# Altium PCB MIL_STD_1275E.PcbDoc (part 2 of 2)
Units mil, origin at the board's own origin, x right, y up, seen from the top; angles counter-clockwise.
Board outline 4000 x 3000 mil, 4 copper layers (Top Layer 1, GND, Signal Layer, Bottom Layer 1), stack 61.2 mil thick; 67 components, 20 nets, 127 pads, 432 vias.
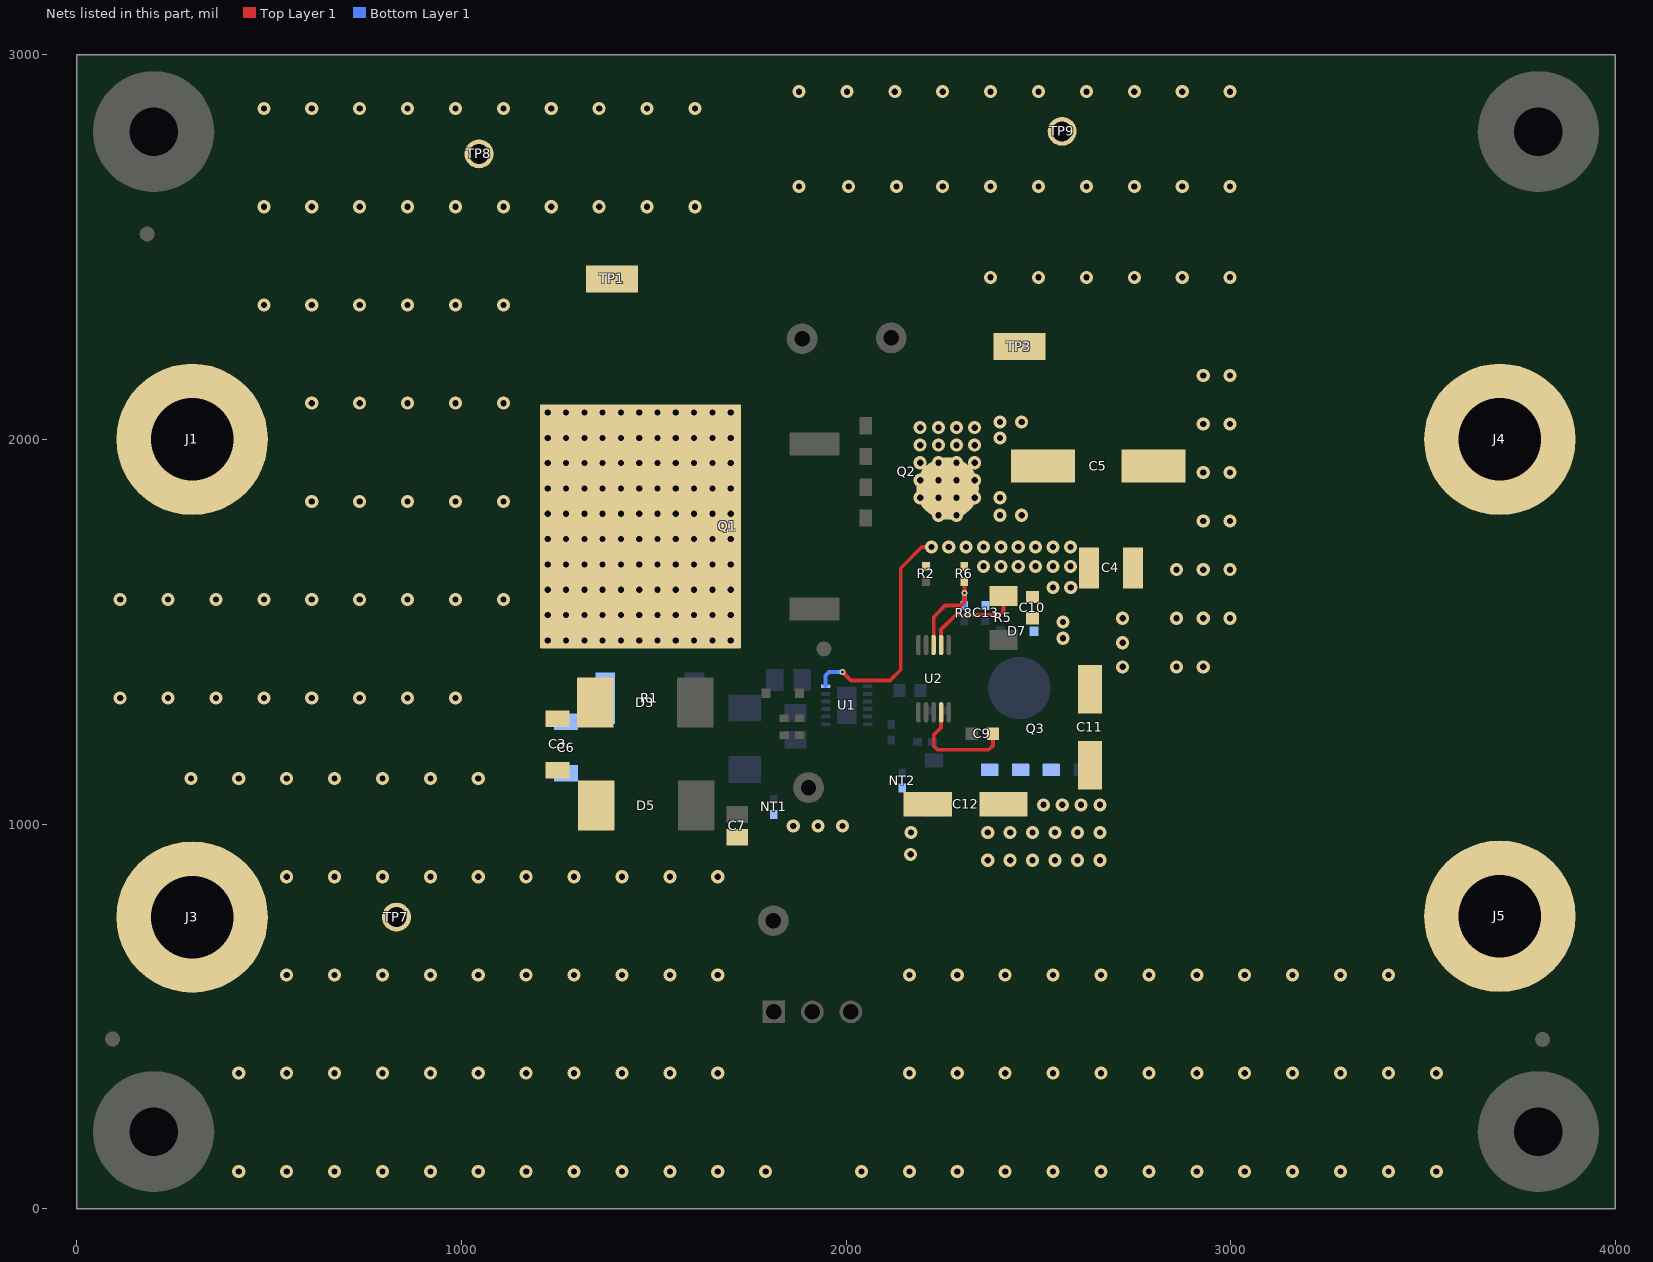
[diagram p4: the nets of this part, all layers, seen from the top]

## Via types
v1: diameter 34, hole 16, Top Layer 1 to Bottom Layer 1, 391 vias
v2: diameter 34, hole 16, Top Layer 1 to Bottom Layer 1, tented both sides, 20 vias
v3: diameter 16, hole 8, Top Layer 1 to Bottom Layer 1, tented both sides, 16 vias
v4: diameter 19.68, hole 7.87, Top Layer 1 to Bottom Layer 1, 3 vias
v5: diameter 34, hole 16, Top Layer 1 to Bottom Layer 1, tented top, 2 vias

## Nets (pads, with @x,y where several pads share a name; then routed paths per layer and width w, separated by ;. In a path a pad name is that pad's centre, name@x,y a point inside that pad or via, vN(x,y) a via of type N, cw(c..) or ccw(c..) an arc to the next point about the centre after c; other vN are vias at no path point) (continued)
SGND: C3.2 C4.2 C5.2 C6.2 C7.2 C10.2 C11.2 C12.2 D5.1 D7.1 J3.1 J5.1 NT1.1 NT2.1 TP7.1 TP8.1 TP9.1
  other v1: 421.23,96.7 545.77,96.7 670.31,96.7 794.85,96.7 919.39,96.7 1043.94,96.7 1168.48,96.7 1293.02,96.7 1417.56,96.7 1542.1,96.7 1666.64,96.7 1791.18,96.7 2040.27,96.7 2164.81,96.7 2289.35,96.7 2413.89,96.7 2538.43,96.7 2662.97,96.7 2787.51,96.7 2912.05,96.7 3036.6,96.7 3161.14,96.7 3285.68,96.7 3410.22,96.7 3534.76,96.7 421.23,352.06 545.77,352.06 670.31,352.06 794.85,352.06 919.39,352.06 1043.94,352.06 1168.48,352.06 1293.02,352.06 1417.56,352.06 1542.1,352.06 1666.64,352.06 2164.81,352.06 2289.35,352.06 2413.89,352.06 2538.43,352.06 2662.97,352.06 2787.51,352.06 2912.05,352.06 3036.6,352.06 3161.14,352.06 3285.68,352.06 3410.22,352.06 3534.76,352.06 545.77,607.42 670.31,607.42 794.85,607.42 919.39,607.42 1043.94,607.42 1168.48,607.42 1293.02,607.42 1417.56,607.42 1542.1,607.42 1666.64,607.42 2164.81,607.42 2289.35,607.42 2413.89,607.42 2538.43,607.42 2662.97,607.42 2787.51,607.42 2912.05,607.42 3036.6,607.42 3161.14,607.42 3285.68,607.42 3410.22,607.42 545.77,862.78 670.31,862.78 794.85,862.78 919.39,862.78 1043.94,862.78 1168.48,862.78 1293.02,862.78 1417.56,862.78 1542.1,862.78 1666.64,862.78 296.69,1118.14 421.23,1118.14 545.77,1118.14 670.31,1118.14 794.85,1118.14 919.39,1118.14 1043.94,1118.14 2859.03,1408.73 2928.86,1408.73 2859.03,1534.94 2928.86,1534.94 2998.7,1534.94 2859.03,1661.15 2928.86,1661.15 2998.7,1661.15 2928.86,1787.36 2998.7,1787.36 2928.86,1913.57 2998.7,1913.57 2928.86,2039.78 2998.7,2039.78 2928.86,2165.99 2998.7,2165.99 2375.99,2421.35 2500.53,2421.35 2625.07,2421.35 2749.61,2421.35 2874.15,2421.35 2998.7,2421.35 1877.82,2657.36 2007.02,2657.36 2131.56,2657.36 2251.45,2657.36 2375.99,2657.36 2500.53,2657.36 2625.07,2657.36 2749.61,2657.36 2874.15,2657.36 2998.7,2657.36 1877.82,2904.01 2002.37,2904.01 2126.91,2904.01 2251.45,2904.01 2375.99,2904.01 2500.53,2904.01 2625.07,2904.01 2749.61,2904.01 2874.15,2904.01 2998.7,2904.01
  other v2: 2168.18,921.17 2168.57,977.8 1862.79,994.82 1926.99,994.82 1991.18,994.82 2719.36,1408.73 2719.36,1471.22 2563.92,1483.02 2563.92,1525.13 2719.36,1534.94
UVLO: R6.1 R8.2 U2.3 | length 255.7
  Top Layer 1 w10: U2.3@2227.71,1465.44 2228.06,1465.78 2228.06,1538.53 2257.33,1567.8 2299.04,1567.8 2307.9,1576.66 v3(2307.9,1600.64) R6.1@2307.9,1630.64
  Bottom Layer 1 w10: R8.2@2307.9,1567.8 v3(2307.9,1600.64)
VIN: C3.1 C6.1 D3.1 J1.1 Q1.4 R1.2 TP1.1
  other v1: 112.85,1328.05 237.39,1328.05 361.93,1328.05 486.47,1328.05 611.01,1328.05 735.56,1328.05 860.1,1328.05 984.64,1328.05 1224.62,1477.31 1272.17,1477.31 1319.73,1477.31 1367.28,1477.31 1414.84,1477.31 1462.39,1477.31 1509.95,1477.31 1557.5,1477.31 1605.06,1477.31 1652.61,1477.31 1700.16,1477.31 1224.62,1543.15 1272.17,1543.15 1319.73,1543.15 1367.28,1543.15 1414.84,1543.15 1462.39,1543.15 1509.95,1543.15 1557.5,1543.15 1605.06,1543.15 1652.61,1543.15 1700.16,1543.15 112.85,1583.41 237.39,1583.41 361.93,1583.41 486.47,1583.41 611.01,1583.41 735.56,1583.41 860.1,1583.41 984.64,1583.41 1109.18,1583.41 1224.62,1608.98 1272.17,1608.98 1319.73,1608.98 1367.28,1608.98 1414.84,1608.98 1462.39,1608.98 1509.95,1608.98 1557.5,1608.98 1605.06,1608.98 1652.61,1608.98 1700.16,1608.98 1224.62,1674.81 1272.17,1674.81 1319.73,1674.81 1367.28,1674.81 1414.84,1674.81 1462.39,1674.81 1509.95,1674.81 1557.5,1674.81 1605.06,1674.81 1652.61,1674.81 1700.16,1674.81 1224.62,1740.65 1272.17,1740.65 1319.73,1740.65 1367.28,1740.65 1414.84,1740.65 1462.39,1740.65 1509.95,1740.65 1557.5,1740.65 1605.06,1740.65 1652.61,1740.65 1700.16,1740.65 1224.62,1806.48 1272.17,1806.48 1319.73,1806.48 1367.28,1806.48 1414.84,1806.48 1462.39,1806.48 1509.95,1806.48 1557.5,1806.48 1605.06,1806.48 1652.61,1806.48 1700.16,1806.48 611.01,1838.77 735.56,1838.77 860.1,1838.77 984.64,1838.77 1109.18,1838.77 1224.62,1872.32 1272.17,1872.32 1319.73,1872.32 1367.28,1872.32 1414.84,1872.32 1462.39,1872.32 1509.95,1872.32 1557.5,1872.32 1605.06,1872.32 1652.61,1872.32 1700.16,1872.32 1224.62,1938.15 1272.17,1938.15 1319.73,1938.15 1367.28,1938.15 1414.84,1938.15 1462.39,1938.15 1509.95,1938.15 1557.5,1938.15 1605.06,1938.15 1652.61,1938.15 1700.16,1938.15 1224.62,2003.99 1272.17,2003.99 1319.73,2003.99 1367.28,2003.99 1414.84,2003.99 1462.39,2003.99 1509.95,2003.99 1557.5,2003.99 1605.06,2003.99 1652.61,2003.99 1700.16,2003.99 1224.62,2069.82 1272.17,2069.82 1319.73,2069.82 1367.28,2069.82 1414.84,2069.82 1462.39,2069.82 1509.95,2069.82 1557.5,2069.82 1605.06,2069.82 1652.61,2069.82 1700.16,2069.82 611.01,2094.13 735.56,2094.13 860.1,2094.13 984.64,2094.13 1109.18,2094.13 486.47,2349.49 611.01,2349.49 735.56,2349.49 860.1,2349.49 984.64,2349.49 1109.18,2349.49 486.47,2604.85 611.01,2604.85 735.56,2604.85 860.1,2604.85 984.64,2604.85 1109.18,2604.85 1233.72,2604.85 1358.26,2604.85 1482.8,2604.85 1607.34,2604.85 486.47,2860.21 611.01,2860.21 735.56,2860.21 860.1,2860.21 984.64,2860.21 1109.18,2860.21 1233.72,2860.21 1358.26,2860.21 1482.8,2860.21 1607.34,2860.21
VOUT: C9.1 C11.1 C12.1 J4.1 Q3.2 Q3.3 Q3.4 U2.9 | length 288.9
  Top Layer 1 w10: U2.9@2247.4,1290.24 2247.4,1250.33 2228.22,1231.16 2228.22,1202.35 2237.6,1192.98 2371.32,1192.98 2382.02,1203.68 C9.1@2382.02,1234.67
  other v1: 2485.18,977.8 2543.48,977.8 2601.77,977.8 2660.06,977.8 2513.2,1049.93 2562.15,1049.93 2611.1,1049.93 2660.06,1049.93
  other v2: 2368.6,905.67 2426.89,905.67 2485.18,905.67 2543.48,905.67 2601.77,905.67 2660.06,905.67 2368.6,977.8 2426.89,977.8
VOUT_LM7480: C4.1 C5.1 C10.1 C13.2 Q2.5 R2.2 R5.1 R6.2 TP3.1 U1.12 U2.2 | length 875.5
  Top Layer 1 w10: v3(1990.48,1395.16) 2012.54,1373.11 2114.16,1373.11 2142.21,1401.16 2142.21,1665.01 2197.06,1719.85 2221.67,1719.85 v1(2221.99,1720.17) ; U2.2@2247.4,1465.44 2247.4,1505.53 2285.83,1543.96 2399.79,1543.96 2409.15,1553.33 R5.1@2409.15,1592.75
  Bottom Layer 1 w10: U1.12@1946.86,1357.98 1946.86,1385.99 1956.04,1395.16 v3(1990.48,1395.16)
  other v1: 2538.2,1614.96 2584.41,1614.96 2357.51,1670.01 2402.68,1670.01 2447.85,1670.01 2493.03,1670.01 2538.2,1670.01 2583.37,1670.01 2267.17,1720.17 2312.34,1720.17 2357.51,1720.17 2402.68,1720.17 2447.85,1720.17 2493.03,1720.17 2538.2,1720.17 2583.37,1720.53 2240.11,1802.75 2287.38,1802.75 2400.07,1802.75 2456.79,1802.75 2192.85,1848.28 2240.11,1848.28 2287.38,1848.28 2334.64,1848.28 2400.07,1848.28 2192.85,1893.8 2240.11,1893.8 2287.38,1893.8 2334.64,1893.8 2192.85,1939.33 2240.11,1939.33 2287.38,1939.33 2334.64,1939.33 2192.85,1984.85 2240.11,1984.85 2287.38,1984.85 2334.64,1984.85 2400.07,2003.99 2192.85,2030.38 2240.11,2030.38 2287.38,2030.38 2334.64,2030.38 2400.07,2045.33 2456.79,2045.33
pads on no net: FID1.1 FID2.1 FID3.1 H1.1 H2.1 H3.1 H4.1 H5.0 H6.0 H7.0 H8.0 LBL1.0 U1.13 U2.8
copper on no net: | length 58.6
  Top Layer 1 w30: 1249.99,1081.39 1249.99,1139.95
  other v4: 2001.59,1269.39 2000.59,1308.76 2001.59,1348.13

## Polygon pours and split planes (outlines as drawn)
SGND on Bottom Layer 1 "BOTTOM_LAYER_1_NONET_P017" (solid, shelved, pour order 17): 24.65,2880.92 118.64,2974.91 3850.18,2974.91 3983.2,2841.89 3975.12,2833.81 3975.12,119.94 3879.15,23.97 150.2,23.97 24.65,149.52
VOUT on Bottom Layer 1 "BOTTOM_LAYER_1_VOUT_P020" (solid, pour order 20): 2301.92,1156.06 2312.4,1166.54 2554.04,1166.54 2570.25,1150.32 2570.25,1109.27 2580.56,1098.95 2660.24,1098.95 2696.8,1062.4 2696.8,889.4 2670.36,862.97 2317.35,862.97 2301.92,878.4
NetQ3_5 on Bottom Layer 1 "BOTTOM_LAYER_1_NETQ3_5_P008" (solid, pour order 8): 2301.92,1430.36 2328.36,1456.79 2646.85,1456.79 2667.38,1436.26 2667.38,1220.31 2648.02,1200.96 2321.41,1200.96 2301.92,1220.45
AGND2 on Bottom Layer 1 "BOTTOM_LAYER_1_AGND2_P001" (solid, pour order 1): 2113.97,1156.71 2128.59,1171.33 2180.92,1171.33 2209.57,1199.98 2209.57,1229.23 2241.39,1261.05 2241.39,1421.92 2174.34,1488.97 2174.34,1531.89 2185.78,1543.34 2408.82,1543.34 2429.31,1522.85 2429.31,1477.23 2422.14,1470.06 2322.77,1470.06 2293.29,1440.57 2293.29,1277.61 2268.73,1253.05 2268.73,1144.58 2237.35,1113.2 2117.77,1113.2 2113.97,1117.01
AGND1 on Bottom Layer 1 "BOTTOM_LAYER_1_AGND1_P002" (solid, pour order 2): 1721.12,1247.77 1918.8,1247.77 1936.41,1265.38 1960.42,1265.38 1993.11,1232.69 2131.99,1232.69 2135.05,1235.75 2135.05,1295.97 2169.87,1330.79 2169.87,1361.37 2177.64,1369.14 2212.69,1369.14 2219.83,1357.98 2219.83,1330.45 2200.59,1311.21 2200.59,1283.73 2161.54,1244.69 2161.54,1187.82 2154.02,1180.3 2115.74,1180.3 1981.54,1046.1 1712.52,1046.1 1685.53,1073.09 1685.53,1212.19
VIN on Bottom Layer 1 "BOTTOM_LAYER_1_VIN_P012" (solid, pour order 12): 1419.38,1223.83 1465.63,1270.08 1465.63,1385.52 1537.36,1457.25 1720.34,1457.25 1729.2,1466.11 1729.2,2951.05 1705.34,2974.91 54.77,2974.91 25.55,2945.69 25.55,1258.08 59.8,1223.83
VOUT_LM7480 on Bottom Layer 1 "BOTTOM_LAYER_1_VOUT_LM7480_P006" (solid, pour order 6): 2137.24,2091.37 2137.24,1662.4 2145.12,1654.51 2322.97,1654.51 2332.17,1645.32 2332.17,1571.09 2352.12,1551.14 2635.82,1551.14 2688.98,1604.31 2688.98,1777.06 2616,1850.04 2616,2090.72 2610.1,2096.61 2142.48,2096.61
NetC8_1 on Bottom Layer 1 "BOTTOM_LAYER_1_NETC8_1_P004" (solid, pour order 4): 1785.88,2323.89 2015.64,2323.89 2021.32,2318.21 2021.32,2015.72 2042.34,1994.7 2073.37,1994.7 2084.9,1983.17 2084.9,1407.41 2073.95,1396.46 2017.13,1396.46 2011.77,1401.83 2011.77,1600.66 2000.93,1611.5 1844.47,1611.5 1830.08,1597.11 1830.08,1516.55 1895.72,1450.91 1895.72,1429.83 1888.24,1422.35 1788.02,1422.35 1778.72,1431.65 1778.72,2316.73
NetC1_1 on Bottom Layer 1 "BOTTOM_LAYER_1_NETC1_1_P000" (solid, pour order 0): 1845.07,1403.51 1841.8,1406.78 1578.91,1406.77 1575.26,1403.13 1575.26,1257.47 1581.19,1251.53 1712.45,1251.53 1716.84,1255.93 1889.7,1255.93 1899.64,1265.87 1899.64,1300.83 1911.23,1312.42 1959.3,1312.42 1960.52,1313.64 1960.52,1323.31 1959.3,1324.53 1918.96,1324.53 1864.59,1324.53 1845.07,1344.05
SGND on Top Layer 1 "TOP_LAYER_1_SGND_P016" (solid, pour order 16): 24.65,2880.92 118.64,2974.91 3850.18,2974.91 3983.2,2841.89 3975.12,2833.81 3975.12,119.94 3879.15,23.97 150.2,23.97 24.65,149.52
VOUT on Top Layer 1 "TOP_LAYER_1_VOUT_P014" (solid, pour order 14): 2301.92,878.4 2301.92,1156.06 2354.33,1208.46 2354.33,1246.35 2376.5,1268.53 2516.15,1268.53 2555.45,1229.23 2816.02,1229.23 3043.59,1456.79 3043.59,2935.23 3088.59,2980.23 3923.35,2980.23 3924.96,2981.84 3973.82,2932.98 3973.82,1086.69 3949,1061.87 3320.26,1061.87 3121.36,862.97 2317.35,862.97
NetC8_1 on Top Layer 1 "TOP_LAYER_1_NETC8_1_P003" (solid, pour order 3): 1785.88,2323.89 2014.83,2323.89 2021.32,2317.4 2021.32,2015.72 2042.34,1994.7 2073.37,1994.7 2081.96,1986.11 2081.96,1758.47 2113.16,1727.27 2113.16,1409.35 2095.31,1391.51 2022.09,1391.51 2011.77,1401.83 2011.77,1600.66 2000.93,1611.5 1844.47,1611.5 1830.08,1597.11 1830.08,1516.55 1895.5,1451.13 1895.5,1405.82 1876.12,1386.44 1823.93,1386.44 1778.79,1431.58 1778.79,2316.8
VIN on Top Layer 1 "TOP_LAYER_1_VIN_P011" (solid, pour order 11): 1419.38,1223.83 1465.63,1270.08 1465.63,1385.52 1513.73,1433.62 1713.29,1433.62 1729.2,1449.53 1729.2,2951.05 1705.34,2974.91 54.77,2974.91 25.55,2945.69 25.55,1258.08 59.8,1223.83
NetQ3_5 on Top Layer 1 "TOP_LAYER_1_NETQ3_5_P007" (solid, pour order 7): 2488.22,1504.33 2533.75,1458.81 2533.75,1286.12 2528.11,1280.49 2307.94,1280.49 2301.92,1286.51 2301.92,1496.51 2309.74,1504.33
VOUT_LM7480 on Top Layer 1 "TOP_LAYER_1_VOUT_LM7480_P005" (solid, pour order 5): 2137.24,2165.3 2137.24,1662.4 2145.12,1654.51 2322.97,1654.51 2332.17,1645.32 2332.17,1584.61 2349.71,1567.07 2651.74,1567.07 2688.98,1604.31 2688.98,1777.06 2616,1850.04 2616,2288.87 2606.16,2298.71 2270.65,2298.71
SGND on GND "GND_SGND_P018" (solid, pour order 18): 24.65,2880.92 118.64,2974.91 3850.18,2974.91 3983.2,2841.89 3975.12,2833.81 3975.12,119.94 3879.15,23.97 150.2,23.97 24.65,149.52
SGND on Signal Layer "SIGNAL_LAYER_SGND_P019" (solid, pour order 19): 24.65,2880.92 118.64,2974.91 3850.18,2974.91 3983.2,2841.89 3975.12,2833.81 3975.12,119.94 3879.15,23.97 150.2,23.97 24.65,149.52

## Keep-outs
Top Layer 1:
  region: 1549.17,1385.98 1554,1390.81 1659.07,1390.81 1665.49,1384.38 1665.49,1091.28 1680.9,1075.86 1755.93,1075.86 1765.49,1066.3 1765.49,1002.36 1758.15,995.02 1676.41,995.02 1641.96,960.57 1554.3,960.57 1549.17,965.7
GND:
  region: 1151.7,2090.38 1190.99,2129.67 1707.72,2129.67 1759.45,2077.94 1759.45,1446.96 1728.26,1415.77 1184.67,1415.77 1151.7,1448.73
Signal Layer:
  region: 1151.3,2090.76 1190.59,2130.05 1707.32,2130.05 1759.05,2078.32 1759.05,1447.34 1727.85,1416.15 1184.26,1416.15 1151.3,1449.11
Keep-Out Layer:
  text ".Layer_Name" at 577,-858.49 h60

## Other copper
Top Layer 1:
  text ".Layer_Name" at 577,-858.49 h60
Bottom Layer 1:
  text ".Layer_Name" at 577,-858.49 h60

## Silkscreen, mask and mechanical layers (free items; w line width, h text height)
Top Overlay:
  lines w10: 1196.77,916.87 2776.34,916.87 2776.34,1702.08 2902.15,1827.89 2902.15,2021.71 2825.89,2097.97 2771.57,2097.97 1196.77,2097.97 1196.77,916.87
  text "SGND" at 2651.7,2810.96 h60
  text "SGND" at 741.75,2742.46 h60
  text "OUT" at 1782.69,2400.19 h60
  text "DGATE" at 2075.85,2400.19 h60
  text "VOUT" at 3490.14,2304.42 h60
  text "VIN" at 1323.85,2280.12 h60
  text "VOUT_LM7480" at 2578.92,2261.6 h60
  text "VIN" at 99.65,2254.98 h60
  text "30mm" at 1166.15,1294.19 h60 r90
  text "SGND" at 91.73,1006.75 h60
  text "AGND1" at 1869.85,989.48 h60
  text "40mm" at 1934.9,834.34 h60
  text "SGND" at 914.08,742.62 h60
  text "VS" at 1602.81,742.62 h60
  text "SGND" at 3414.24,403.45 h60
  text "VS" at 1835.92,318.25 h60 r90
  text "'.PRJ_Number'.PCB_Rev" at 2328.39,171.27 h108.27
  text "AGND1" at 2047.31,158.3 h60 r90
  text "ENABLE" at 1941.13,78.33 h60 r90
  text ".Layer_Name" at 577,-858.49 h60
Bottom Overlay:
  lines w10: 1196.77,902.12 2771.57,902.12 2771.57,2097.97 1196.77,2097.97 1196.77,902.12
  text ".Layer_Name" at 577,-858.49 h60
Top Paste:
  text ".Layer_Name" at 577,-858.49 h60
Bottom Paste:
  text ".Layer_Name" at 577,-858.49 h60
Top Solder:
  text ".Layer_Name" at 577,-858.49 h60
  text ".Layer_Name" at 577,-858.49 h60
Bottom Solder:
  text ".Layer_Name" at 577,-858.49 h60
Drill Guide:
  text ".Layer_Name" at 577,-858.49 h60
M1 Board Outline:
  lines w10: 0,0 0,2999.93 4000,2999.93 4000,0 0,10
  text ".Layer_Name" at 577,-858.49 h60
M2 Board Dimensions:
  rectangle: 0,-275 125,-150
  rectangle: 125,-400 500,-275
  lines w7: 0,-275 1000,-275 ; 125,-400 125,-150 ; 250,-400 250,-150 ; 500,-400 500,-150 ; 750,-400 750,-150 ; 0,-400 1000,-400 1000,-150 0,-150 0,-400
  text ".Layer_Name" at 577,-858.49 h60
M3 3D STEP Top:
  text ".Layer_Name" at 577,-858.49 h60
M4 3D STEP Bottom:
  text ".Layer_Name" at 577,-858.49 h60
M5 Assembly Top:
  lines w10: -292,-930.17 6308,-930.17 ; -292,-726.83 6310,-726.83 ; -292,-523.5 -292,-1133.5 3713,-1133.5 6310,-1133.5 6310,-523.5 -291.5,-523.5 -291.5,-1133.5 1284,-1133.5 ; 2173,-1133.5 2173,-523.5 ; 3440,-726.83 3440,-523.5 ; 4280,-726.83 4280,-523.5 ; 4902,-1140 4902,-937.17
  text "COMPONENTS MARKED 'DNP' SHOULD NOT BE POPULATED." at 1153.5,-318.5 h60
  text "ASSEMBLY VARIANT:" at 1153,-434 h60
  text ".VariantName" at 2189,-434 h60
  text "PCB VIEWED FROM TOP SIDE" at -228.5,-655.67 h60
  text "BOARD #:" at 2248,-655.67 h60
  text ".PRJ_Number" at 2793.5,-655.67 h60
  text "REV:" at 3638,-655.67 h60
  text ".PCB_Rev" at 3929.5,-655.67 h60
  text "SVN REV:" at 4476,-655.67 h60
  text ".VersionControl_RevNumber" at 4982,-655.67 h60
  text "TID #:" at 2248,-859 h60
  text ".TID" at 2793.5,-859 h60
  text "PLOT NAME =" at -228.5,-1064.34 h60
  text ".plot_File_Name" at 577,-1064.34 h60
  text "GENERATED    :" at 2250,-1064.34 h60
  text ".Print_Date" at 3119.5,-1064.34 h60
  text ".Print_Time" at 3848.5,-1064.34 h60
  text "TEXAS INSTRUMENTS" at 5113,-1064.34 h60
M6 Assembly Bottom:
  lines w10: -292.5,-727.33 6309.5,-727.33 ; -290.5,-930.67 6309.5,-930.67 ; 1115.5,-1140.5 1115.5,-937.67 ; 1737.5,-727.33 1737.5,-524 ; 2577.5,-727.33 2577.5,-524 ; 3844.5,-1134 3844.5,-524 ; 4733.5,-1134 6309,-1134 6309,-524 -292.5,-524 -292.5,-1134 2304.5,-1134 6309.5,-1134 6309.5,-524
  text "COMPONENTS MARKED 'DNP' SHOULD NOT BE POPULATED." at 6102,-318 h60
  text ".VariantName" at 5058,-434 h60
  text "ASSEMBLY VARIANT:" at 6097,-434 h60
  text ".VersionControl_RevNumber" at 1035.5,-656.17 h60
  text "SVN REV:" at 1541.5,-656.17 h60
  text ".PCB_Rev" at 2088,-656.17 h60
  text "REV:" at 2379.5,-656.17 h60
  text ".PRJ_Number" at 3224,-656.17 h60
  text "BOARD #:" at 3769.5,-656.17 h60
  text "PCB VIEWED FROM BOTTOM SIDE" at 6246,-656.17 h60
  text ".TID" at 3224,-859.5 h60
  text "TID #:" at 3769.5,-859.5 h60
  text "TEXAS INSTRUMENTS" at 904.5,-1064.84 h60
  text ".Print_Time" at 2169,-1064.84 h60
  text ".Print_Date" at 2898,-1064.84 h60
  text "GENERATED    :" at 3767.5,-1064.84 h60
  text ".plot_File_Name" at 5440.5,-1064.84 h60
  text "PLOT NAME =" at 6246,-1064.84 h60
M9 Title Sheet:
  drawing of 57 lines, arcs and shapes, not listed
  text "1" at 739.84,8036.5 h70
  text "2" at 3235.5,8036.5 h70
  text "3" at 5724.84,8036.5 h70
  text "4" at 8231.51,8036.5 h70
  text "5" at 10730.5,8036.5 h70
  text "6" at 13235.5,8036.5 h70
  text "A" at -416.5,6893.5 h70
  text "A" at 14383.5,6893.5 h70
  text "B" at -416.5,4513.5 h70
  text "B" at 14383.5,4513.5 h70
  text "C" at -416.5,2138.5 h70
  text "C" at 14383.5,2138.5 h70
  text "PROJECT TITLE:" at 11343.5,277.5 h45
  text ".PRJ_Title" at 11393.5,144.17 h70
  text "DESIGNED FOR:" at 11343.5,-23.5 h45
  text ".PRJ_Customer" at 11393.5,-163.5 h70
  text "D" at -416.5,-231.5 h70
  text "D" at 14383.5,-231.5 h70
  text "FILE NAME:" at 11343.5,-323.5 h45
  text ".PCB_File_Name_No_Path" at 11393.5,-443.5 h70
  text "Texas Instruments (TI) and/or its licensors do not warrant the accuracy or completeness of this specification" at 6374,-605.34 h45
  text "ENGINEER:" at 11343.5,-613.5 h45
  text "LAYOUT BY:" at 12848.5,-613.5 h45
  text "or any information contained therein. TI and/or its licensors do not warrant that this design will meet" at 6329.01,-718 h45
  text ".PRJ_Engineer" at 11393.5,-768.49 h70
  text ".PCB_Layout" at 12899,-768.49 h70
  text "the specifications, will be suitable for your application or fit for any particular purpose, or will operate in" at 6329.01,-830.67 h45
  text ".Layer_Name" at 577,-858.49 h60
  text "ALTIUM DESIGNER VERSION:" at 12848.5,-923.5 h45
  text "an implementation. TI and/or its licensors do not warrant that the design is production worthy. You should" at 6329.01,-943.33 h45
  text "completely validate and test your design implementation to confirm the system functionality for your application." at 6374,-1056 h45
  text ".print_Scale" at 11393.5,-1056.83 h70
  text ".Application_BuildNumber" at 12899,-1056.83 h70
  text "1" at 739.84,-1263.5 h70
  text "2" at 3235.5,-1263.5 h70
  text "3" at 5724.84,-1263.5 h70
  text "4" at 8231.51,-1263.5 h70
  text "5" at 10730.5,-1263.5 h70
  text "6" at 13235.5,-1263.5 h70
M10 Fab Notes:
  drawing of 189 lines, arcs and shapes, not listed
  text "DESIGN INFORMATION" at 12382.02,6356.17 h60
  text "MIN. TRACK WIDTH:" at 11737.46,6224.05 h60
  text "8" at 12833.7,6224.05 h60
  text "MIL" at 12988.46,6224.05 h60
  text "7.874" at 12667.32,6102.36 h60
  text "MIN. CLEARANCE:" at 11737.46,6099.92 h60
  text "MIL" at 12988.46,6099.92 h60
  text "MIN. VIA PAD SIZE:" at 11737.46,5975.8 h60
  text "24" at 12803.71,5975.8 h60
  text "MIL" at 12988.46,5975.8 h60
  text "0.05mm (2MIL)" at 12432.46,5845.9 h60
  text "MINIMUM ANNULAR RING" at 11408.23,5837.67 h60
  text "EXTERNAL" at 13140.46,5837.67 h60
  text "PER" at 11608.23,5727.55 h60
  text "IPC-D-275 CLASS 2 LEVEL C" at 11828.23,5727.54 h60
  text "MIL, HOLES" at 13316.46,5627.07 h60
  text "+/-" at 12924,5618.48 h60
  text "+/-" at 13778,5618.48 h60
  text "REGISTRATION TOLERANCES:" at 11408.23,5617.42 h60
  text "METAL" at 12608,5617.42 h60
  text "5" at 13184.2,5617.42 h60
  text "3" at 14017.2,5617.42 h60
  text "MIL" at 14133.46,5617.42 h60
  text "HOLE SIZE TOLERANCE (UNLESS OTHERWISE SPECIFIED):" at 11408.23,5519.1 h60
  text "+/-" at 13778,5516.23 h60
  text "3" at 14017.2,5515.17 h60
  text "MIL" at 14133.46,5515.17 h60
  text "MATERIAL:" at 11333.46,5377.52 h60
  text "FR-4 High Tg" at 12319.9,5249 h60
  text "X" at 12175.46,5241.01 h60
  text "FR-408" at 11754.46,5236.49 h60
  text "OTHER" at 13242.46,5236.49 h60
  text "62 MIL (1.6mm) +/-10%" at 12074.56,5093.46 h60
  text "X" at 11954.46,5091.01 h60
  text "THICKNESS:" at 11408.23,5085.24 h60
  text "OTHER" at 13359.46,5085.24 h60
  text "TOLERANCE:" at 11408.23,4946.92 h60
  text "X" at 12256.46,4946.92 h60
  text "ANSI IPC-6012 TYPE 3 CLASS 2" at 12434.48,4946.92 h60
  text "OTHER +/-" at 12434.46,4802.73 h60
  text "BOW & TWIST:" at 11408.23,4657.54 h60
  text "X" at 12256.46,4657.54 h60
  text "ANSI IPC-6012 TYPE 3 CLASS 2" at 12434.48,4657.54 h60
  text "OTHER +/-" at 12434.46,4510.85 h60
  text "DRILLING:" at 11333.46,4380.23 h60
  text "NC_DRILL FILES" at 13094.46,4275.04 h60
  text "REFERENCE:" at 11408.23,4271.1 h60
  text "X" at 12065.46,4271.01 h60
  text "AS SHOWN" at 12243.46,4271.1 h60
  text "X" at 12966.46,4271.1 h60
  text "OTHER" at 13392.46,4128.85 h60
  text "PTH COPPER THICKNESS:" at 11407.91,4125.32 h60
  text "X" at 12547.14,4125.32 h60
  text "20-30 um" at 12675.14,4125.32 h60
  text "BOARD FINISH:" at 11333.46,3977.73 h60
  text "SILKSCREEN:" at 11488.68,3867.6 h60
  text "X" at 12446.46,3867.6 h60
  text "TOP" at 12563.46,3867.6 h60
  text "X" at 12956.46,3867.6 h60
  text "BOTTOM" at 13074.46,3867.6 h60
  text "SILKSCREEN COLOR:" at 11488.68,3712.41 h60
  text "X" at 12445.46,3712.41 h60
  text "WHITE" at 12563.46,3712.41 h60
  text "OTHER" at 13074.46,3712.41 h60
  text "X" at 12576.46,3568.96 h60
  text "GREEN" at 12694.46,3568.96 h60
  text "OTHER" at 13312.46,3568.96 h60
  text "SOLDER RESIST COLOR:" at 11488.68,3562.1 h60
  text "X" at 12576.46,3414.71 h60
  text "MATTE" at 12694.46,3414.71 h60
  text "SEMI-GLOSS" at 13312,3414.07 h60
  text "IMMERSION GOLD (ENIG)" at 12394.46,3241.94 h60
  text "ENEPIG" at 13732,3234.72 h60
  text "SURFACE FINISH:" at 11333.46,3233.72 h60
  text "X" at 12216.46,3233.72 h60
  text "IMM. TIN/SILVER OR EQUIV" at 11663,3096.4 h60
  text "OTHER" at 13094.46,3092.47 h60
  text "ARRAY/PANEL:" at 11333.46,2937.09 h60
  text "CUT AND TRIM PER M1 BOARD OUTLINE" at 12394.46,2928.87 h60
  text "N.C. ROUTE" at 12394.46,2792.9 h60
  text "X" at 13082.46,2792.9 h60
  text "V. SCORE" at 13260.46,2792.9 h60
  text "CERTIFICATION:" at 11333.46,2663.77 h60
  text "MATERIALS AND WORKMANSHIP FOR ALL PCBS" at 12058.46,2663.77 h60
  text "TO MEET OR EXCEED THE REQUIREMENTS OF:" at 12058.46,2569.71 h60
  text "X" at 11695.97,2441.08 h60
  text "ANSI IPC-A-600F CLASS ->" at 11823.96,2441.08 h60
  text "X" at 13471.97,2441.08 h60
  text "2" at 13581.96,2441.08 h60
  text "1" at 13266.96,2439.58 h60
  text "3" at 13935.96,2439.58 h60
  text "X" at 12507.97,2293.39 h60
  text "RoHS" at 12635.96,2293.39 h60
  text "OTHER" at 13280.36,2293.39 h60
  text "PER ORDER" at 13677.42,2293.39 h60
  text "ALL BOARDS MUST MEET OR EXCEED UL94-V0 REQUIREMENTS." at 11361,2139.57 h60
  text "PCB MUST BEAR THE UL94V-0 UL REGISTERED MATERIAL ID NUMBER" at 11361,2023.5 h60
  text "ADDITIONAL REQUIREMENTS:" at 11333.46,1854.08 h60
  text "MICROSECTION:" at 11408.23,1746.95 h60
  text "YES" at 12313.96,1746.95 h60
  text "REQUIRED" at 13175.46,1602.62 h60
  text "BARE BOARD ELEC. TEST:" at 11408.23,1599.76 h60
  text "NONE" at 12713.96,1599.76 h60
  text "X" at 13057.46,1599.76 h60
  text "PER ORDER" at 13767.46,1599.76 h60
  text "XX MIL VIAS REQUIRE NON-CONDUCTIVE FILL AND PLANARIZE" at 11576.38,1394.82 h59
  text "XX MIL VIAS REQUIRE CONDUCTIVE FILL AND PLANARIZE" at 11584.38,1290.84 h60
  text "OUTER XX MIL TRACES REQUIRE 50 OHM SINGLE-ENDED IMPEDANCE" at 11583.39,1127.46 h58
  text "LAYER 2 & 3 (INNER LAYERS) XX MIL WIDE, XX MIL SPACE / TRACES REQUIRE 100 OHM DIFFERENTIAL IMPEDANCE" at 11575.39,891.74 h60
  text ".Layer_Name" at 577,-858.49 h60
M11 Gerber Information:
  lines w10: -292,-930.17 6308,-930.17 ; -292,-726.83 6310,-726.83 ; -292,-523.5 -292,-1133.5 3713,-1133.5 6310,-1133.5 6310,-523.5 -291.5,-523.5 -291.5,-1133.5 1284,-1133.5 ; 2173,-1133.5 2173,-523.5 ; 3440,-726.83 3440,-523.5 ; 4280,-726.83 4280,-523.5 ; 4902,-1140 4902,-937.17
  text "ALL ARTWORK VIEWED FROM TOP SIDE" at -228.5,-655.67 h60
  text "BOARD #:" at 2248,-655.67 h60
  text ".PRJ_Number" at 2793.5,-655.67 h60
  text "REV:" at 3638,-655.67 h60
  text ".PCB_Rev" at 3929.5,-655.67 h60
  text "SVN REV:" at 4476,-655.67 h60
  text ".VersionControl_RevNumber" at 4982,-655.67 h60
  text "LAYER NAME =" at -228.5,-858.49 h60
  text "TID #:" at 2248,-859 h60
  text ".TID" at 2793.5,-859 h60
  text "PLOT NAME =" at -228.5,-1064.34 h60
  text ".plot_File_Name" at 577,-1064.34 h60
  text "GENERATED    :" at 2250,-1064.34 h60
  text ".Print_Date" at 3119.5,-1064.34 h60
  text ".Print_Time" at 3848.5,-1064.34 h60
  text "TEXAS INSTRUMENTS" at 5113,-1064.34 h60
M12 Stackup:
  drawing of 295 lines, arcs and shapes, not listed
  text "Layer" at 9821.59,7874.94 h60
  text "Name" at 10231.51,7874.94 h60
  text "Material" at 11161.25,7874.94 h60
  text "Thickness" at 12021.02,7874.94 h60
  text "Constant" at 12670.85,7874.94 h60
  text "Board Layer Stack" at 13240.71,7874.94 h60
  text "Top Overlay" at 10231.51,7754.94 h60
  text "Top Solder" at 10231.51,7634.94 h60
  text "Solder Resist" at 11161.25,7634.94 h60
  text "0.40mil" at 12021.02,7634.94 h60
  text "3.5" at 12670.85,7634.94 h60
  text "1" at 9821.59,7514.94 h60
  text "Top Layer 1" at 10231.51,7514.94 h60
  text "CF-004" at 11161.25,7514.94 h60
  text "1.38mil" at 12021.02,7514.94 h60
  text "Dielectric 1" at 10231.51,7394.94 h60
  text "PP-006" at 11161.25,7394.94 h60
  text "2.80mil" at 12021.02,7394.94 h60
  text "4.1" at 12670.85,7394.94 h60
  text "2" at 9821.59,7274.94 h60
  text "GND" at 10231.51,7274.94 h60
  text "1.40mil" at 12021.02,7274.94 h60
  text "Dielectric1" at 10231.51,7154.94 h60
  text "FR-4 High Tg" at 11161.25,7154.94 h60
  text "50.04mil" at 12021.02,7154.94 h60
  text "4.8" at 12670.85,7154.94 h60
  text "3" at 9821.59,7034.94 h60
  text "Signal Layer" at 10231.51,7034.94 h60
  text "1.40mil" at 12021.02,7034.94 h60
  text "Dielectric 2" at 10231.51,6914.94 h60
  text "PP-006" at 11161.25,6914.94 h60
  text "2.80mil" at 12021.02,6914.94 h60
  text "4.1" at 12670.85,6914.94 h60
  text "4" at 9821.59,6794.94 h60
  text "Bottom Layer 1" at 10231.51,6794.94 h60
  text "CF-004" at 11161.25,6794.94 h60
  text "1.38mil" at 12021.02,6794.94 h60
  text "Bottom Solder" at 10231.51,6674.94 h60
  text "Solder Resist" at 11161.25,6674.94 h60
  text "0.40mil" at 12021.02,6674.94 h60
  text "3.5" at 12670.85,6674.94 h60
  text "Bottom Overlay" at 10231.51,6554.94 h60
  text ".Layer_Name" at 577,-858.49 h60
M13 Component Bodies Top:
  text ".Layer_Name" at 577,-858.49 h60
M14 Component Bodies Bottom:
  text ".Layer_Name" at 577,-858.49 h60
M15 Courtyards Top:
  text ".Layer_Name" at 577,-858.49 h60
M16 Courtyards Bottom:
  text ".Layer_Name" at 577,-858.49 h60
Drill Drawing:
  circle w10: c5363.72,2917.32 r27.63
  lines w10: 5336.09,2516.74 5391.34,2516.74 5391.34,2571.99 5336.09,2571.99 5336.09,2516.74 ; 5336.09,2654.87 5349.9,2654.87 5363.72,2641.06 5377.53,2654.87 5391.34,2654.87 5377.53,2668.68 5391.34,2682.5 5377.53,2682.5 5363.72,2696.31 5349.9,2682.5 5336.09,2682.5 5349.9,2668.68 5336.09,2654.87 ; 5336.09,2820.63 5391.34,2820.63 5363.72,2765.38 5336.09,2820.63 ; 5336.09,3014.02 5363.72,3027.83 5391.34,3014.02 5377.53,3041.64 5391.34,3069.27 5363.72,3055.46 5336.09,3069.27 5349.9,3041.64 5336.09,3014.02 ; 5336.09,3152.15 5349.9,3152.15 5349.9,3138.34 5377.53,3138.34 5377.53,3152.15 5391.34,3152.15 5391.34,3179.78 5377.53,3179.78 5377.53,3193.59 5349.9,3193.59 5349.9,3179.78 5336.09,3179.78 5336.09,3152.15 ; 5336.09,3262.66 5336.09,3276.47 5349.9,3290.28 5336.09,3304.1 5336.09,3317.91 5349.9,3317.91 5363.72,3304.1 5377.53,3317.91 5391.34,3317.91 5391.34,3304.1 5377.53,3290.28 5391.34,3276.47 5391.34,3262.66 5377.53,3262.66 5363.72,3276.47 5349.9,3262.66 5336.09,3262.66
  lines w12: 5286,2479.44 8597.63,2479.44 ; 5286,3349.68 8597.63,3349.68 ; 5623.86,2355.12 5623.86,3474 ; 5955.86,2355.12 5955.86,3474 ; 6592.43,2355.12 6592.43,3474 ; 6851.57,2355.12 6851.57,3474 ; 7226.72,2355.12 7226.72,3474 ; 8031.2,2355.12 8031.2,3474 ; 5286,2355.12 8597.63,2355.12 8597.63,3474 5286,3474 5286,2355.12
  text "Symbol" at 5360.59,3386.98 h72
  text "Quantity" at 5661.16,3386.98 h72
  text "Finished Hole Size" at 5993.16,3386.98 h72
  text "Plated" at 6629.72,3386.98 h72
  text "Hole Type" at 6888.86,3386.98 h72
  text "Drill Layer Pair" at 7264.02,3386.98 h72
  text "Hole Tolerance" at 8068.49,3386.98 h72
  text "3" at 5661.16,3262.66 h60
  text "7.87mil (0.200mm)" at 5993.16,3262.66 h60
  text "PTH" at 6629.72,3262.66 h60
  text "Round" at 6888.86,3262.66 h60
  text "Top Layer 1 - Bottom Layer 1" at 7264.02,3262.66 h60
  text "16" at 5661.16,3138.34 h60
  text "8.00mil (0.203mm)" at 5993.16,3138.34 h60
  text "PTH" at 6629.72,3138.34 h60
  text "Round" at 6888.86,3138.34 h60
  text "Top Layer 1 - Bottom Layer 1" at 7264.02,3138.34 h60
  text "+0.00mil/-8.00mil" at 8068.49,3138.34 h60
  text "413" at 5661.16,3014.02 h60
  text "16.00mil (0.406mm)" at 5993.16,3014.02 h60
  text "PTH" at 6629.72,3014.02 h60
  text "Round" at 6888.86,3014.02 h60
  text "Top Layer 1 - Bottom Layer 1" at 7264.02,3014.02 h60
  text "+0.00mil/-16.00mil" at 8068.49,3014.02 h60
  text "7" at 5661.16,2889.7 h60
  text "40.00mil (1.016mm)" at 5993.16,2889.7 h60
  text "PTH" at 6629.72,2889.7 h60
  text "Round" at 6888.86,2889.7 h60
  text "Top Layer 1 - Bottom Layer 1" at 7264.02,2889.7 h60
  text "3" at 5661.16,2765.38 h60
  text "52.00mil (1.321mm)" at 5993.16,2765.38 h60
  text "PTH" at 6629.72,2765.38 h60
  text "Round" at 6888.86,2765.38 h60
  text "Top Layer 1 - Bottom Layer 1" at 7264.02,2765.38 h60
  text "4" at 5661.16,2641.06 h60
  text "125.98mil (3.200mm)" at 5993.16,2641.06 h60
  text "PTH" at 6629.72,2641.06 h60
  text "Round" at 6888.86,2641.06 h60
  text "Top Layer 1 - Bottom Layer 1" at 7264.02,2641.06 h60
  text "4" at 5661.16,2516.74 h60
  text "214.57mil (5.450mm)" at 5993.16,2516.74 h60
  text "PTH" at 6629.72,2516.74 h60
  text "Round" at 6888.86,2516.74 h60
  text "Top Layer 1 - Bottom Layer 1" at 7264.02,2516.74 h60
  text "450 Total" at 5661.16,2392.42 h60
  text ".Layer_Name" at 577,-858.49 h60
M17 Embedded Cavity:
  text ".Layer_Name" at 577,-858.49 h60
M18 Embedded Assembly:
  text ".Layer_Name" at 577,-858.49 h60
M19 Embedded Keepout:
  text ".Layer_Name" at 577,-858.49 h60

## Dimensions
0,-400 to 1000,-400 on M2 Board Dimensions
0,0 to 0,3000 on M2 Board Dimensions
0,0 to 4000,0 on M2 Board Dimensions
